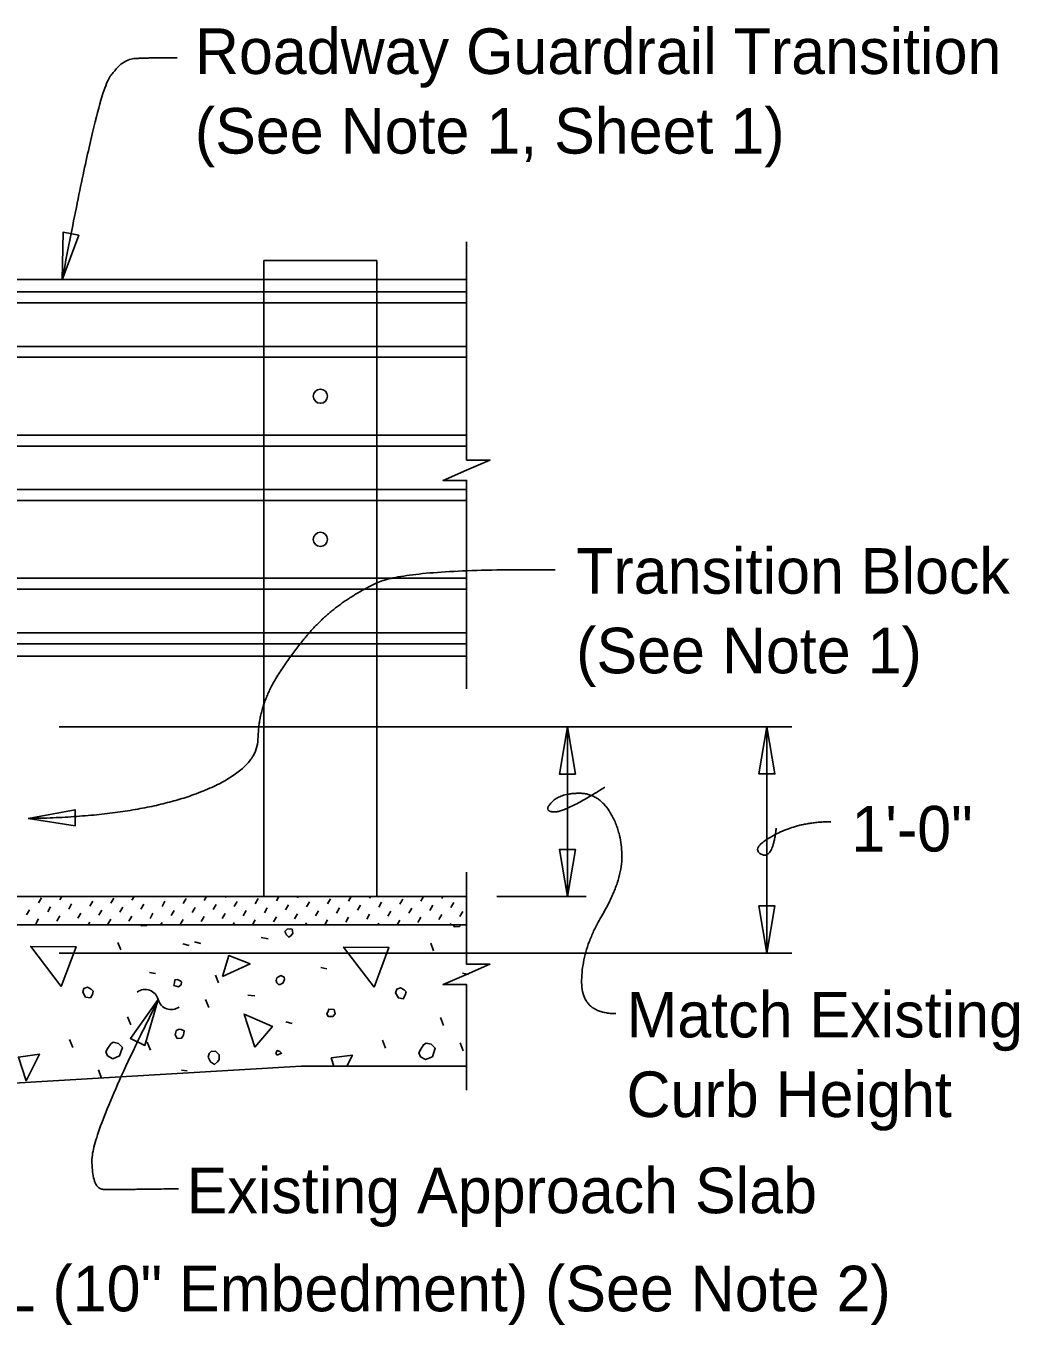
# Model space of a CAD drawing. Extents: x 21526.6 to 21598.7, y 56118.1 to 56155.9.
# Drawn here: x 21539.73 to 21544.13, y 56132.57 to 56138.31 of the extents above; entities that cross this region are included whole.
import ezdxf

# ---------------------------------------------------------------- set-up
doc = ezdxf.new("R2010")
doc.units = 0
for name, color, linetype in [('AdhocPoint_dp', 7, 'Continuous'), ('Border', 7, 'Continuous'), ('Patterning', 7, 'Continuous'), ('PlotBorder_dp', 7, 'Continuous'), ('SheetBorder_dp', 7, 'Continuous')]:
    doc.layers.add(name, color=color, linetype=linetype)

msp = doc.modelspace()

# ---------------------------------------------------------------- linework, layer by layer
at = {"layer": 'AdhocPoint_dp'}
for p, q in [((21535.7321, 56134.4601), (21541.6829, 56134.4601)), ((21537.582, 56134.335), (21541.6829, 56134.335)), ((21536.7321, 56133.4601), (21540.9521, 56133.71)), ((21540.9521, 56133.7101), (21541.6829, 56133.7101))]:
    msp.add_line(p, q, dxfattribs=at)
at = {"layer": 'Patterning'}
for p, q in [((21540.7867, 56137.2725), (21540.7867, 56134.4601)), ((21540.7867, 56137.2725), (21541.2867, 56137.2725)), ((21541.2867, 56137.2725), (21541.2867, 56134.4601)), ((21539.7909, 56134.4317), (21539.8039, 56134.4541)), ((21539.884, 56134.4447), (21539.8929, 56134.46)), ((21539.9771, 56134.4577), (21539.9785, 56134.46)), ((21540.1103, 56134.4306), (21540.1232, 56134.4529)), ((21540.2034, 56134.4435), (21540.2129, 56134.46)), ((21540.2965, 56134.4565), (21540.2985, 56134.46)), ((21540.4297, 56134.4294), (21540.4426, 56134.4518)), ((21540.5228, 56134.4423), (21540.533, 56134.46)), ((21540.6159, 56134.4553), (21540.6186, 56134.46)), ((21540.749, 56134.4282), (21540.762, 56134.4506)), ((21540.8421, 56134.4412), (21540.8531, 56134.46)), ((21540.9352, 56134.4541), (21540.9387, 56134.46)), ((21541.0684, 56134.427), (21541.0814, 56134.4494)), ((21541.1615, 56134.44), (21541.1731, 56134.46)), ((21541.2546, 56134.4529), (21541.2587, 56134.46)), ((21541.3878, 56134.4258), (21541.4008, 56134.4482)), ((21541.4809, 56134.4388), (21541.4932, 56134.46)), ((21541.574, 56134.4518), (21541.5788, 56134.46)), ((21539.7379, 56134.3787), (21539.7508, 56134.4011)), ((21539.831, 56134.3917), (21539.8439, 56134.4141)), ((21539.9241, 56134.4046), (21539.937, 56134.427)), ((21539.9641, 56134.3646), (21539.9771, 56134.387)), ((21540.0172, 56134.4176), (21540.0301, 56134.44)), ((21540.0572, 56134.3775), (21540.0702, 56134.3999)), ((21540.1504, 56134.3905), (21540.1633, 56134.4129)), ((21540.2435, 56134.4034), (21540.2564, 56134.4258)), ((21540.3366, 56134.4164), (21540.3495, 56134.4388)), ((21540.3766, 56134.3763), (21540.3896, 56134.3987)), ((21540.4697, 56134.3893), (21540.4827, 56134.4117)), ((21540.5628, 56134.4023), (21540.5758, 56134.4247)), ((21540.6559, 56134.4152), (21540.6689, 56134.4376)), ((21540.696, 56134.3752), (21540.709, 56134.3976)), ((21540.7891, 56134.3881), (21540.8021, 56134.4105)), ((21540.8822, 56134.4011), (21540.8952, 56134.4235)), ((21540.9753, 56134.4141), (21540.9883, 56134.4364)), ((21541.0154, 56134.374), (21541.0283, 56134.3964)), ((21541.1085, 56134.387), (21541.1214, 56134.4093)), ((21541.2016, 56134.3999), (21541.2145, 56134.4223)), ((21541.2947, 56134.4129), (21541.3077, 56134.4353)), ((21541.3348, 56134.3728), (21541.3477, 56134.3952)), ((21541.4279, 56134.3858), (21541.4408, 56134.4082)), ((21541.521, 56134.3987), (21541.5339, 56134.4211)), ((21541.6141, 56134.4117), (21541.627, 56134.4341)), ((21541.6541, 56134.3716), (21541.6671, 56134.394)), ((21539.7779, 56134.3386), (21539.7909, 56134.361)), ((21539.871, 56134.3516), (21539.884, 56134.374)), ((21540.0103, 56134.335), (21540.0172, 56134.3469)), ((21540.0973, 56134.3375), (21540.1103, 56134.3598)), ((21540.1904, 56134.3504), (21540.2034, 56134.3728)), ((21540.2835, 56134.3634), (21540.2965, 56134.3858)), ((21540.3304, 56134.335), (21540.3366, 56134.3457)), ((21540.4167, 56134.3363), (21540.4297, 56134.3587)), ((21540.5098, 56134.3492), (21540.5228, 56134.3716)), ((21540.6029, 56134.3622), (21540.6159, 56134.3846)), ((21540.6504, 56134.335), (21540.6559, 56134.3445)), ((21540.7361, 56134.3351), (21540.749, 56134.3575)), ((21540.8292, 56134.3481), (21540.8421, 56134.3705)), ((21540.9223, 56134.361), (21540.9352, 56134.3834)), ((21540.9705, 56134.335), (21540.9753, 56134.3433)), ((21541.0561, 56134.335), (21541.0684, 56134.3563)), ((21541.1486, 56134.3469), (21541.1615, 56134.3693)), ((21541.2417, 56134.3598), (21541.2546, 56134.3822)), ((21541.2905, 56134.335), (21541.2947, 56134.3422)), ((21541.3761, 56134.335), (21541.3878, 56134.3551)), ((21541.4679, 56134.3457), (21541.4809, 56134.3681)), ((21541.561, 56134.3587), (21541.574, 56134.3811)), ((21541.6106, 56134.335), (21541.6141, 56134.341)), ((21540.7756, 56134.2785), (21540.8056, 56134.2732)), ((21540.1542, 56134.2237), (21540.1418, 56134.2573)), ((21540.4282, 56134.2502), (21540.4565, 56134.2431)), ((21540.4799, 56134.2595), (21540.5082, 56134.2524)), ((21541.5375, 56134.2202), (21541.5251, 56134.2537)), ((21540.2815, 56134.1247), (21540.308, 56134.1194)), ((21540.586, 56134.0783), (21540.5736, 56134.1119)), ((21541.0389, 56134.1459), (21541.0655, 56134.1406)), ((21541.6647, 56134.1212), (21541.6913, 56134.1159)), ((21540.5435, 56133.9687), (21540.5294, 56134.004)), ((21540.7154, 56134.0239), (21540.7473, 56134.0204)), ((21540.1984, 56133.8931), (21540.1842, 56133.9285)), ((21540.8834, 56133.9055), (21540.9117, 56133.8984)), ((21541.5817, 56133.8896), (21541.5675, 56133.9249)), ((21539.9421, 56133.7924), (21539.9279, 56133.8277)), ((21540.2854, 56133.7813), (21540.2713, 56133.8167)), ((21541.3253, 56133.7888), (21541.3112, 56133.8242)), ((21541.6687, 56133.7778), (21541.6546, 56133.8131)), ((21540.0676, 56133.6598), (21540.0552, 56133.6934)), ((21540.4233, 56133.6929), (21540.4481, 56133.6894))]:
    msp.add_line(p, q, dxfattribs=at)
for points in [[(21540.2429, 56134.335), (21540.2461, 56134.3298), (21540.2691, 56134.3315), (21540.2725, 56134.335)], [(21541.624, 56134.335), (21541.6294, 56134.3262), (21541.6524, 56134.328), (21541.6594, 56134.335)], [(21540.8869, 56134.2909), (21540.8975, 56134.2803), (21540.9081, 56134.2873), (21540.9152, 56134.2979), (21540.9117, 56134.3156), (21540.9028, 56134.3174), (21540.8905, 56134.3156), (21540.8799, 56134.305), (21540.8869, 56134.2909)], [(21539.8908, 56134.0628), (21539.7564, 56134.2396), (21539.9562, 56134.2378), (21539.8908, 56134.0628)], [(21541.2741, 56134.0593), (21541.1397, 56134.2361), (21541.3395, 56134.2343), (21541.2741, 56134.0593)], [(21540.6041, 56134.107), (21540.6324, 56134.1989), (21540.7261, 56134.1618), (21540.6041, 56134.107)], [(21540.8516, 56134.0717), (21540.8586, 56134.0717), (21540.8728, 56134.0787), (21540.8781, 56134.0946), (21540.8763, 56134.1035), (21540.8622, 56134.1106), (21540.8445, 56134.0999), (21540.841, 56134.0893), (21540.8445, 56134.0787), (21540.8516, 56134.0717)], [(21539.9898, 56134.031), (21539.9986, 56134.0151), (21540.0198, 56134.0116), (21540.0287, 56134.0275), (21540.0322, 56134.0416), (21540.0234, 56134.0505), (21540.0075, 56134.0593), (21539.9915, 56134.054), (21539.9862, 56134.0381), (21539.9898, 56134.031)], [(21540.3893, 56134.0664), (21540.4087, 56134.0611), (21540.4211, 56134.0699), (21540.4229, 56134.0823), (21540.4193, 56134.0858), (21540.4052, 56134.0929), (21540.3928, 56134.0911), (21540.3911, 56134.0787), (21540.3893, 56134.0664)], [(21541.3731, 56134.0275), (21541.3819, 56134.0116), (21541.4031, 56134.008), (21541.4119, 56134.0239), (21541.4155, 56134.0381), (21541.4066, 56134.0469), (21541.3907, 56134.0558), (21541.3748, 56134.0505), (21541.3695, 56134.0345), (21541.3731, 56134.0275)], [(21540.7468, 56133.7937), (21540.6991, 56133.9404), (21540.8246, 56133.8856), (21540.7468, 56133.7937)], [(21541.0708, 56133.9302), (21541.092, 56133.9302), (21541.1026, 56133.9409), (21541.0973, 56133.9603), (21541.0743, 56133.9621), (21541.0708, 56133.9515), (21541.0655, 56133.9426), (21541.0708, 56133.9302), (21541.0672, 56133.9338)], [(21540.395, 56133.8485), (21540.4039, 56133.8326), (21540.4233, 56133.8343), (21540.4322, 56133.8467), (21540.4339, 56133.8662), (21540.4216, 56133.8715), (21540.4127, 56133.8732), (21540.4021, 56133.8697), (21540.3986, 56133.8662), (21540.395, 56133.8485)], [(21540.0958, 56133.7552), (21540.1188, 56133.7429), (21540.1489, 56133.7552), (21540.1613, 56133.7924), (21540.1436, 56133.81), (21540.1206, 56133.8153), (21540.11, 56133.8083), (21540.0976, 56133.7888), (21540.0888, 56133.7729), (21540.0958, 56133.7552)], [(21539.7352, 56133.6456), (21539.7016, 56133.7499), (21539.7953, 56133.7623), (21539.7352, 56133.6456)], [(21540.54, 56133.7495), (21540.5506, 56133.7283), (21540.5683, 56133.7177), (21540.5824, 56133.7283), (21540.5895, 56133.7389), (21540.5895, 56133.7601), (21540.5736, 56133.776), (21540.5541, 56133.7742), (21540.5453, 56133.7654), (21540.54, 56133.7495)], [(21540.8458, 56133.7583), (21540.8653, 56133.7672), (21540.8582, 56133.7742), (21540.8458, 56133.7795), (21540.8405, 56133.7672), (21540.8458, 56133.7583)], [(21541.0966, 56133.71), (21541.0849, 56133.7464), (21541.1786, 56133.7588), (21541.1535, 56133.71)], [(21541.4791, 56133.7517), (21541.5021, 56133.7393), (21541.5322, 56133.7517), (21541.5445, 56133.7888), (21541.5269, 56133.8065), (21541.5039, 56133.8118), (21541.4933, 56133.8047), (21541.4809, 56133.7853), (21541.4721, 56133.7694), (21541.4791, 56133.7517)], [(21540.9547, 56133.71), (21540.9537, 56133.7106), (21540.9522, 56133.71)]]:
    msp.add_lwpolyline(points, dxfattribs=at)
at = {"layer": 'PlotBorder_dp'}
for p, q in [((21539.8821, 56135.2101), (21543.1218, 56135.2101)), ((21542.129, 56135.2101), (21542.129, 56134.4601)), ((21543.0111, 56135.2102), (21543.0111, 56134.2102)), ((21541.8169, 56134.4601), (21542.2116, 56134.4601)), ((21539.8821, 56134.2101), (21543.1218, 56134.2101))]:
    msp.add_line(p, q, dxfattribs=at)
for points in [[(21539.8946, 56137.1866), (21539.9683, 56137.3845), (21539.899, 56137.3977)], [(21542.129, 56135.2101), (21542.0937, 56135.0018), (21542.1642, 56135.0018)], [(21543.0111, 56135.2102), (21542.9758, 56135.0019), (21543.0464, 56135.0019)], [(21539.7444, 56134.8051), (21539.9532, 56134.7733), (21539.9521, 56134.8439)], [(21542.129, 56134.4601), (21542.1642, 56134.6683), (21542.0937, 56134.6683)], [(21543.0111, 56134.2102), (21543.0464, 56134.4184), (21542.9758, 56134.4184)], [(21540.3202, 56134.0044), (21540.1971, 56133.8327), (21540.2605, 56133.8018)]]:
    msp.add_lwpolyline(points, close=True, dxfattribs=at)
for points in [[(21541.6829, 56135.3777), (21541.6829, 56136.3003), (21541.5795, 56136.3003), (21541.6829, 56136.3453), (21541.7862, 56136.3903), (21541.6829, 56136.3903), (21541.6829, 56137.3551)], [(21541.6829, 56133.6036), (21541.6829, 56134.0708), (21541.5795, 56134.0708), (21541.6829, 56134.1158), (21541.7862, 56134.1608), (21541.6829, 56134.1608), (21541.6829, 56134.5682)]]:
    msp.add_lwpolyline(points, dxfattribs=at)
for centre, start, end in [((21540.2618, 56133.9896), 14.54134, 126.26856), ((21540.3772, 56134.0195), 194.54134, 306.26856)]:
    msp.add_arc(centre, 0.0596, start, end, dxfattribs=at)
for points in [[(21540.4034, 56138.1693), (21540.2833, 56138.1693), (21540.1525, 56138.1622), (21540.0465, 56137.9819), (21539.8946, 56137.1866)], [(21542.0754, 56135.9047), (21541.4139, 56135.9116), (21541.1398, 56135.7744), (21540.9568, 56135.6032), (21540.7613, 56135.3058), (21540.7613, 56135.0162), (21540.2137, 56134.8128), (21539.7444, 56134.8049)], [(21542.3427, 56133.9425), (21542.1919, 56133.9425), (21542.1919, 56134.2238), (21542.3701, 56134.5256), (21542.3701, 56134.7451), (21542.2673, 56134.9166), (21542.0959, 56134.9166), (21542.0206, 56134.8343), (21542.1234, 56134.8343), (21542.2947, 56134.944)], [(21543.0526, 56134.7626), (21543.0366, 56134.6212), (21542.9352, 56134.6732), (21543.1526, 56134.7906), (21543.2939, 56134.7906)], [(21540.4101, 56133.1678), (21540.1274, 56133.1634), (21540.0268, 56133.1666), (21540.0268, 56133.4222), (21540.3202, 56134.0043)]]:
    msp.add_open_spline(points, degree=2, dxfattribs=at)
at = {"layer": 'SheetBorder_dp'}
for p, q in [((21541.6829, 56137.1892), (21534.1592, 56137.1892)), ((21534.1592, 56137.1336), (21541.6829, 56137.1336)), ((21534.1592, 56137.0854), (21541.6829, 56137.0854)), ((21534.1592, 56136.8926), (21541.6829, 56136.8926)), ((21534.1592, 56136.8444), (21541.6829, 56136.8444)), ((21534.1592, 56136.5004), (21541.6829, 56136.5004)), ((21534.1592, 56136.4522), (21541.6829, 56136.4522)), ((21534.1592, 56136.2594), (21541.6829, 56136.2594)), ((21534.1592, 56136.2112), (21541.6829, 56136.2112)), ((21534.1592, 56135.8673), (21541.6829, 56135.8673)), ((21534.1592, 56135.8191), (21541.6829, 56135.8191)), ((21534.1592, 56135.6262), (21541.6829, 56135.6262)), ((21534.1592, 56135.578), (21541.6829, 56135.578)), ((21541.6829, 56135.5225), (21534.1592, 56135.5225))]:
    msp.add_line(p, q, dxfattribs=at)
for centre in [(21541.0367, 56136.6724), (21541.0367, 56136.0393)]:
    msp.add_circle(centre, 0.0312, dxfattribs=at)

# ---------------------------------------------------------------- texts
at = {"layer": 'Border'}
for s, p in [('1\'-0"', (21543.3847, 56134.659)), ('Existing Approach Slab', (21540.4455, 56133.0596)), ('Dowel Bars 4L (10" Embedment) (See Note 2)', (21538.0238, 56132.6259))]:
    msp.add_text(s, height=0.2016, dxfattribs=at).set_placement(p)
at = {"layer": 'PlotBorder_dp'}
for s, p in [('Roadway Guardrail Transition', (21540.4819, 56138.0972)), ('(See Note 1, Sheet 1)', (21540.4819, 56137.7452)), ('Transition Block', (21542.1678, 56135.799)), ('(See Note 1)', (21542.1678, 56135.447)), ('Match Existing ', (21542.3904, 56133.8368)), ('Curb Height', (21542.3904, 56133.4848))]:
    msp.add_text(s, height=0.2016, dxfattribs=at).set_placement(p)

doc.saveas('drawing.dxf')
